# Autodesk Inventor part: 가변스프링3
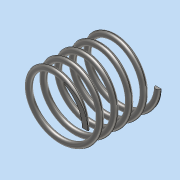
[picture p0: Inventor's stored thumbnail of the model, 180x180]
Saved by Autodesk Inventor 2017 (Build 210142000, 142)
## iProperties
Part Number: 가변스프링3
Material: 강철, 연강
Document SubType Name: Modeling
Designer: MRC
Density: 7.85 g/cm^3
Appearance: 반연마
Mass: 8.37402 g
Surface Area: 21.6501 cm^2
Volume: 1.06675 cm^3
Author: MRC
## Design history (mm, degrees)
sketch "스케치1"
  geometry: L1 (0, 0)-(0, 25.358); L2 (0, 0)-(11, 0); L3 (0, 25.358)-(11, 25.358); C1 r 1 at (11, 0)
  constraints: 6 end point, 2 horizontal, 1 centre point, 1 coincident, 1 vertical
  dimensions: "d0" = 25.35829 distance of L1.start L1.end (derived); "d1" = 11 distance of L1.start L2.end; "d2" = 2 diameter of C1
feature "코일1" pitch "d3" = 10; turns "d5" = 5; dims "d4" = 25.35829 (= d0), "d6" = 0, angle "d7" = 90 deg, angle "d8" = 90 deg, "d9" = 0, "d10" = 0
sketch "스케치2"
  geometry: L1 (25.358, 15)-(0, 15); L2 (0, 15)-(0, -15); L3 (0, -15)-(25.358, -15); L4 (25.358, -15)-(25.358, 15); 2 further points
  constraints: 8 end point, 2 parallel, 1 coincident, 1 horizontal, 1 midpoint, 1 perpendicular
  dimensions: "d11" = 30 distance of L3.end L1.start; "d12" = 25.35829 distance of L2.end L3.end (= d0)
extrude "돌출1" sketch "스케치2" stored distance "d13" = 30; taper "d14" = 0 deg
node "솔리드1"
